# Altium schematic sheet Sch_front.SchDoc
size A
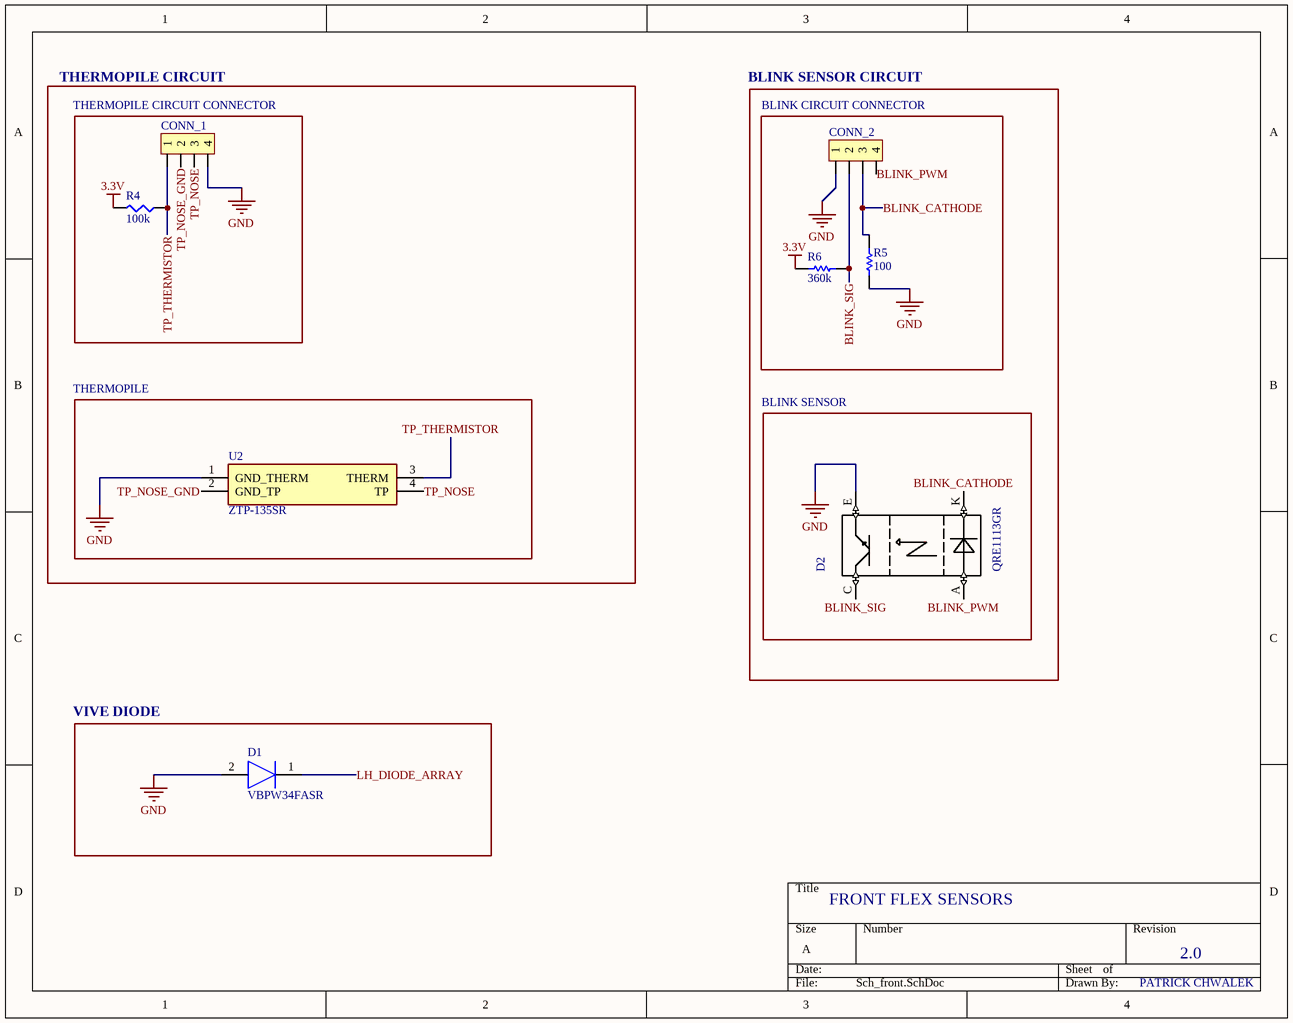
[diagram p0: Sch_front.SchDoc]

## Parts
CONN_1  THERMO  [4_pos_1mm_header]  (value not drawn)
CONN_2  BLINK  [4_pos_1mm_header]  (value not drawn)
D1  VBPW34FASR  [VBPW34FAS]
D2  QRE1113GR  [*4LEADSMD_QRE1113GR(Primary)]
R4  100k  [SMD-0402-RES]
R5  100  [0402R]
R6  360k  [0402R]
U2  ZTP-135SR  [ZTP-135SR]

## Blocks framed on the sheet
THERMOPILE CIRCUIT CONNECTOR: CONN_1 R4
BLINK CIRCUIT CONNECTOR: CONN_2 R5 R6
THERMOPILE: U2
BLINK SENSOR: D2
VIVE DIODE: D1

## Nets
3.3V: R4.2 R6.2
GND: CONN_1.4 CONN_2.1 D1.2(K) D2.E R5.1 U2.1(GND_THERM)
BLINK_CATHODE: CONN_2.3 D2.K R5.2
BLINK_PWM: CONN_2.4 D2.A
BLINK_SIG: CONN_2.2 D2.C R6.1
LH_DIODE_ARRAY: D1.1(A)
TP_NOSE: CONN_1.3 U2.4(TP)
TP_NOSE_GND: CONN_1.2 U2.2(GND_TP)
TP_THERMISTOR: CONN_1.1 R4.1 U2.3(THERM)

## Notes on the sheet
- THERMOPILE CIRCUIT
- BLINK SENSOR CIRCUIT
- FRONT FLEX SENSORS
- 2.0
- PATRICK CHWALEK

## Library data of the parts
CONN_1 CONN_2 = 4_pin_1mm_header
D1 = VBPW34FASR: Diode; Manufacturer_Name: Vishay
D2 = QRE1113GR: QRE1113 Series 30 V 50 mA Miniature Reflective Object Sensor - SMD-4; MF: ON Semiconductor
R4 = ERJ-2GEJ104X: RES SMD 100K OHM 5% 1/10W 0402; Manufacturer: Panasonic Electronic Components; Factory Stock: 0; Unit Price (USD): 0.00350; @ qty: 1500; Minimum Quantity: 1; Power (Watts): 0.1W, 1/10W; Temperature Coefficient: ±200ppm/°C
R5 = Resistor
R6 = Resistor: RC0402FR-07360KL
U2 = ZTP-135SR: Undefined or Miscellaneous; Manufacturer_Name: Amphenol Advanced Sensors; Allied_Number: 70282698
